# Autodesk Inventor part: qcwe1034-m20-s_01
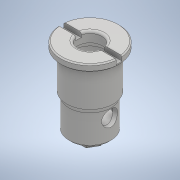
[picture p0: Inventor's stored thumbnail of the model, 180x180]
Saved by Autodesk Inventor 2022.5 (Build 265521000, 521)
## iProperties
Created: 2020-10
Part Number: qcwe1034-m20-s_01
Material: 一般
Document SubType Name: Modeling
Designer: ImaoCorp
Density: 1 g/cm^3
Appearance: 既定
Author: ImaoCorp
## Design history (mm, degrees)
feature "qcwe1034-m20-s_01"
node "ソリッド1"
